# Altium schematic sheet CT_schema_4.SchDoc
size 279 x 211 mm
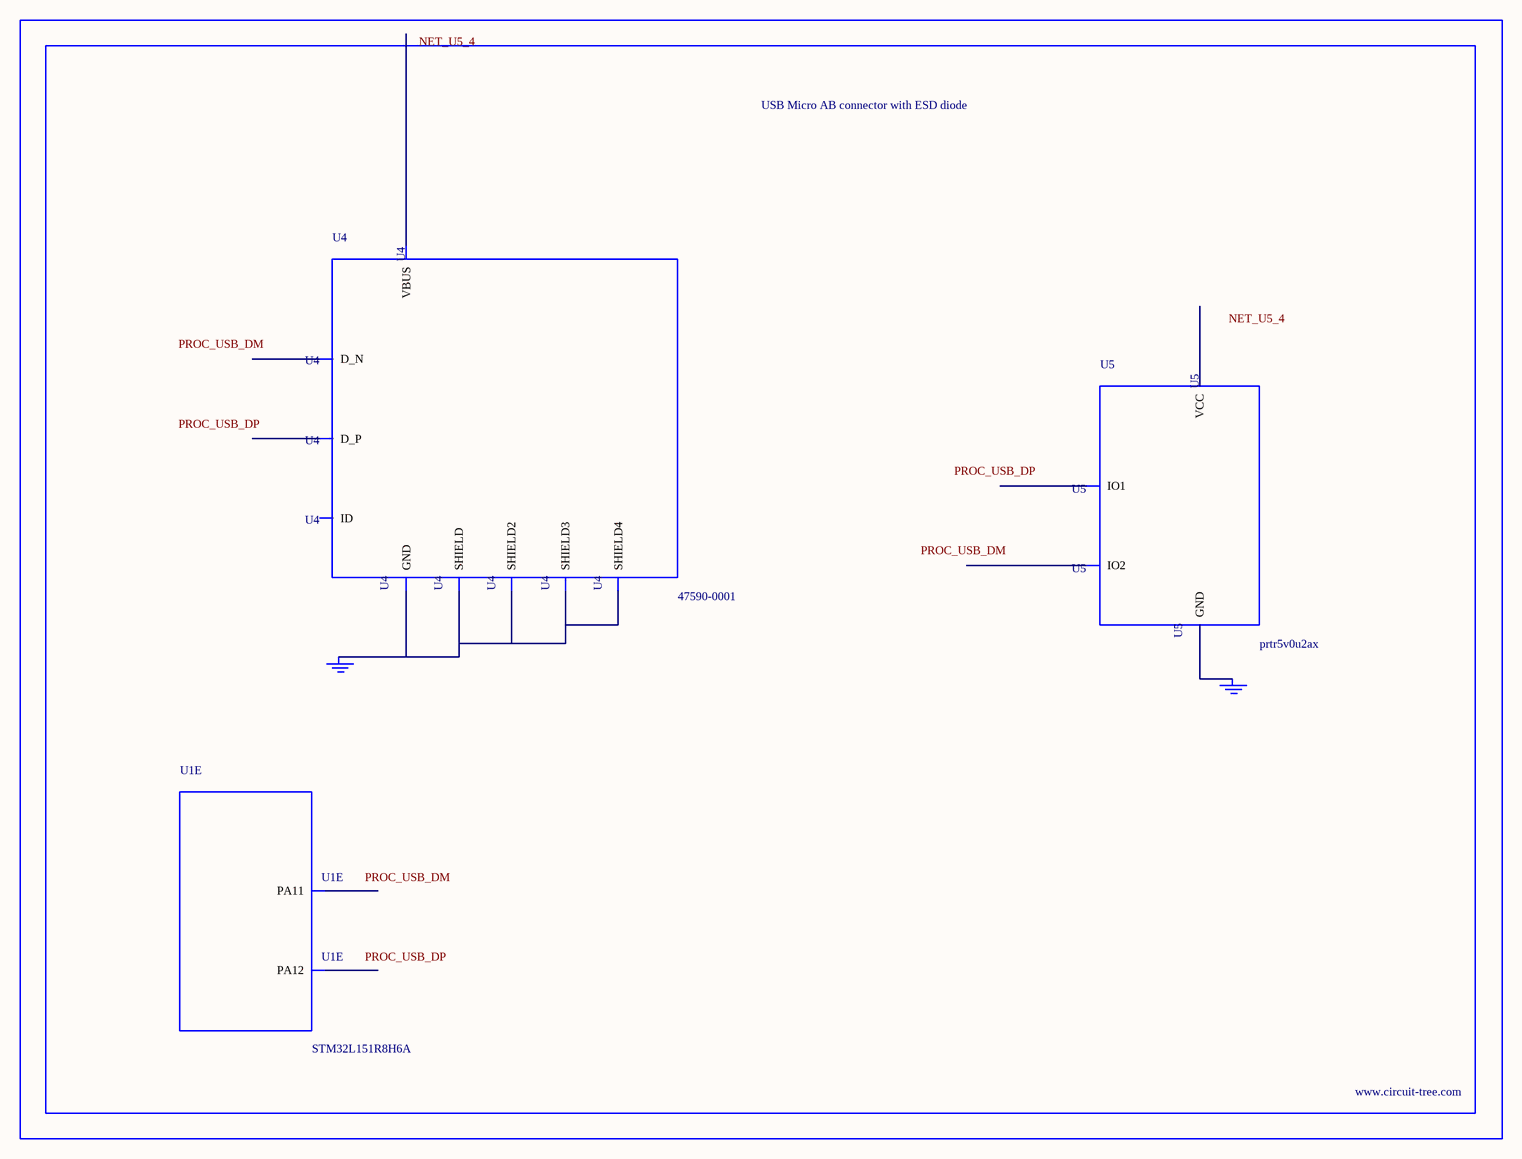
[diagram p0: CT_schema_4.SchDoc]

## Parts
BORDER3  (no value)
GND_INSTANCE_3_0  (no value)
GND_INSTANCE_3_1  (no value)
U1  STM32L151R8H6A  [TFBGA64]  (part E of 7)
U4  47590-0001  [MICRO_USB_AB]
U5  prtr5v0u2ax  [SOT143B]

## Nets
NetGND_INSTANCE_3_0_0: GND_INSTANCE_3_0.0(GND) U4.5(GND) U4.6(SHIELD) U4.7(SHIELD2) U4.8(SHIELD3) U4.9(SHIELD4)
NetGND_INSTANCE_3_1_0: GND_INSTANCE_3_1.0(GND) U5.1(GND)

Not connected (* = marked no-connect by the designer): U1 B8(PA12) C8(PA11); U4 1(VBUS) 2(D_N) 3(D_P) 4(ID); U5 2(IO1) 3(IO2) 4(VCC)

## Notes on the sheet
- Labels drawn without touching a wire or pin: NET_U5_4, PROC_USB_DM, PROC_USB_DP

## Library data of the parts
BORDER3 = BORDER_PAGE3
GND_INSTANCE_3_0 GND_INSTANCE_3_1 = GND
